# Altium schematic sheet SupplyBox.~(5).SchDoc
size B; SheetNumber: 1; SheetTotal: 1
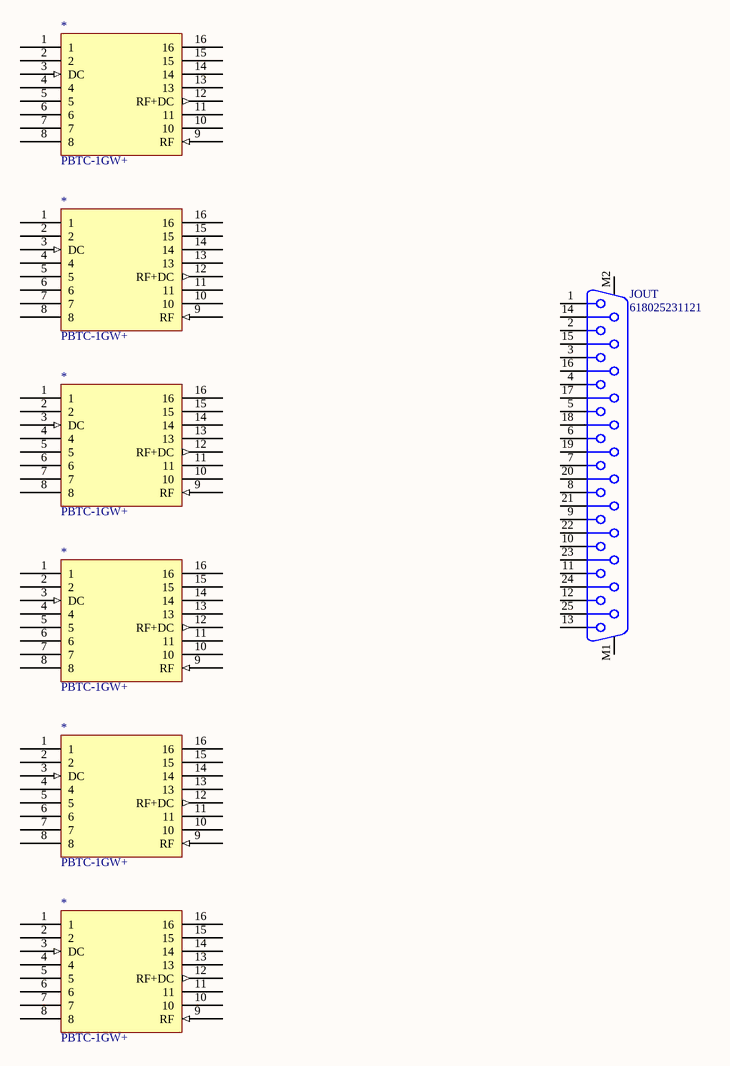
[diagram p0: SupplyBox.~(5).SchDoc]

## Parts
(Parts that share a designator on the sheet are numbered #1, #2 ... from top to bottom, then left to right.)
*#1  PBTC-1GW+  [PBTC-1GW+]
*#2  PBTC-1GW+  [PBTC-1GW+]
*#3  PBTC-1GW+  [PBTC-1GW+]
*#4  PBTC-1GW+  [PBTC-1GW+]
*#5  PBTC-1GW+  [PBTC-1GW+]
*#6  PBTC-1GW+  [PBTC-1GW+]
JOUT  618025231121  [618025231121]

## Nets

Not connected (* = marked no-connect by the designer): *#1 1 2 3(DC) 4 5 6 7 8 9(RF) 10 11 12(RF+DC) 13 14 15 16; *#2 1 2 3(DC) 4 5 6 7 8 9(RF) 10 11 12(RF+DC) 13 14 15 16; *#3 1 2 3(DC) 4 5 6 7 8 9(RF) 10 11 12(RF+DC) 13 14 15 16; *#4 1 2 3(DC) 4 5 6 7 8 9(RF) 10 11 12(RF+DC) 13 14 15 16; *#5 1 2 3(DC) 4 5 6 7 8 9(RF) 10 11 12(RF+DC) 13 14 15 16; *#6 1 2 3(DC) 4 5 6 7 8 9(RF) 10 11 12(RF+DC) 13 14 15 16; JOUT 1 2 3 4 5 6 7 8 9 10 11 12 13 14 15 16 17 18 19 20 21 22 23 24 25 M1 M2

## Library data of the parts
*#1-*#6 = CMP-00025-00003-1: Monitor TEE DC Block, 0.1MHz Min, 1000MHz Max, 1dB Insertion Loss-Max
JOUT = CMP-1502-00202-2: NexarPartId: 18818207; Pitch: 2.77mm; Operating Supply Voltage: 125V; Gender: Female; Insulation Resistance: 5GΩ; Contact Resistance: 30mΩ; Current Rating: 3A; Number of Contacts: 25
